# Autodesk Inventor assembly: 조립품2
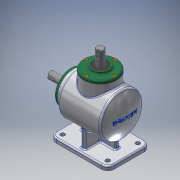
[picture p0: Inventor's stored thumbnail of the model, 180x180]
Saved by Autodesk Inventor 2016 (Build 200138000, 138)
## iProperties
Created: 2016-09
Part Number: 조립품2
Document SubType Name: Assembly
Designer: Administrator
Author: Administrator
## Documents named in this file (14)
- D:\460907V1005\조립품2.iam
- D:\460907V1005\부품1.ipt
- D:\460907V1005\커버.ipt
- D:\460907V1005\M4.ipt
- D:\460907V1005\오일실 17 32 8.ipt
- D:\460907V1005\베어링 6203.ipt
- D:\460907V1005\메인 축.ipt
- 메인 축.ipt
- D:\460907V1005\키 5x5.ipt
- D:\460907V1005\서브 축.ipt
- 서브 축.ipt
- D:\460907V1005\키 4x4.ipt
- D:\460907V1005\메인 베벨기어.ipt
- D:\460907V1005\서브 베벨기어.ipt
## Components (8 placed, 1 different names)
1. M4:1
2. M4:2
3. M4:3
4. M4:4
5. M4:5
6. M4:6
7. M4:7
8. M4:8
